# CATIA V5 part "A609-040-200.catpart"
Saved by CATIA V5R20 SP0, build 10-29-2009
Part number: A609-040-200
Source: Unknown
Property "ARTICLENO": "A609-040-200"
Property "B": "30.000"
Property "BOMINFO": "A609-040-200"
Property "CODE": "A609-040-200"
Property "D": "20.000"
Property "D1": "13.500"
Property "FORM": "B"
Property "L": "200.000"
Property "L1": "25.000"
Property "L2": "75.000"
Property "LINA": "A609-040-200"
Property "NB": "A609-040-200"
Property "NBSYN": "$CODE."
Property "NN": "A609"
Property "NT": "VDI 3357 E-Type Wear Plates, self-lubricating"
Property "S": "40.000"
Property "SUPPLIER": "CF"
Property "T": "13.000"
Property "W": "60.000"
Bounding box of the stored display mesh (mm): x 0 to 200, y 0 to 40, z 0 to 60
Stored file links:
  C:\Users\Utente\Desktop\3D files A609\A609-040-200.catpart
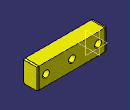
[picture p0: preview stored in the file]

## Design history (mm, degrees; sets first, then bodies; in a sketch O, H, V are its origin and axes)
Body1 "Geometry.1" (main body)
  Solid1 "A609-040-200.catpart": solid without history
